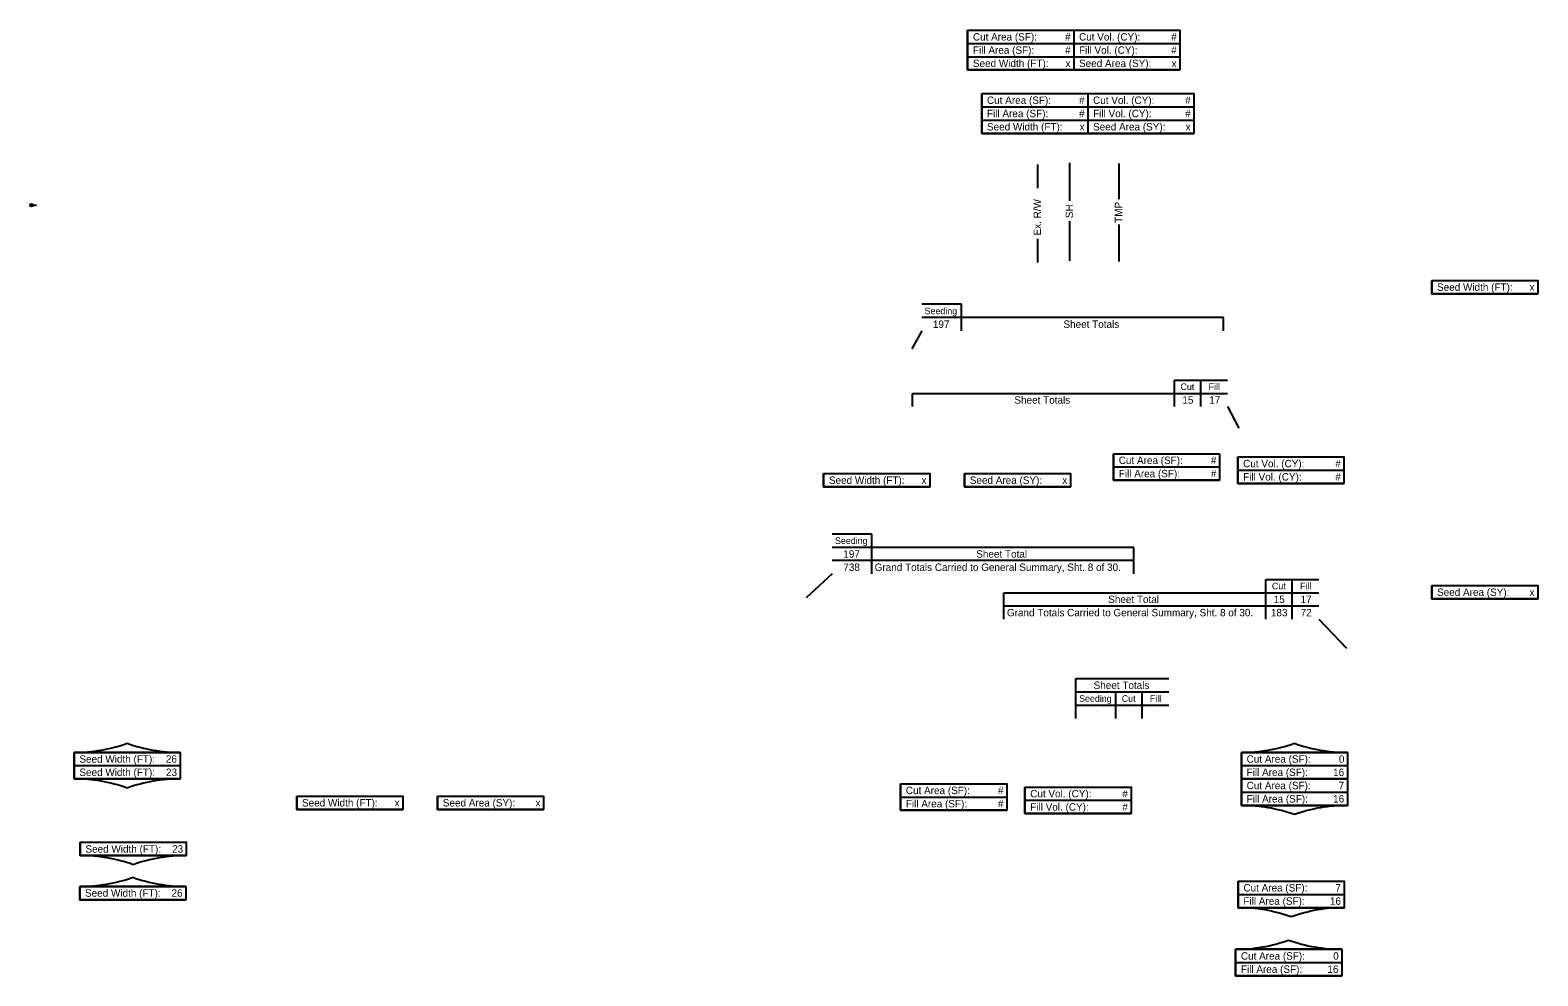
# Model space of a CAD drawing. Extents: x -475 to 76, y 0 to 417.
# Drawn here: x -32.79 to -4.37, y -0.22 to 17.6 of the extents above; entities that cross this region are included whole.
import ezdxf

# ---------------------------------------------------------------- set-up
doc = ezdxf.new("R2010")
doc.units = 0
for name, color, linetype in [('_CIVIL_CONSTRUCTION', 7, 'Continuous'), ('Default', 7, 'Continuous'), ('MT_P_Temp_Road', 7, 'Continuous'), ('RW_P_Esmt_SH', 7, 'Continuous'), ('RW_P_Esmt_TMP', 7, 'Continuous'), ('RW_X_Text', 7, 'Continuous'), ('SC_Scratch1', 7, 'Continuous'), ('SC_Scratch10', 7, 'Continuous'), ('SH_Masking', 7, 'Continuous')]:
    doc.layers.add(name, color=color, linetype=linetype)

msp = doc.modelspace()

# ---------------------------------------------------------------- linework, layer by layer
at = {"layer": '_CIVIL_CONSTRUCTION'}
for p, q in [((-32.791, 14.303), (-32.739, 14.303)), ((-32.765, 14.303), (-32.671, 14.303))]:
    msp.add_line(p, q, dxfattribs=at)
msp.add_circle((-32.765, 14.303), 0.026, dxfattribs=at)
at = {"layer": 'Default'}
for p, q in [((-15.237, 11.935), (-15.237, 12.435)), ((-10.301, 11.935), (-10.301, 12.185)), ((-11.225, 10.507), (-11.225, 11.007)), ((-10.725, 10.507), (-10.725, 11.007)), ((-16.161, 10.507), (-16.161, 10.757)), ((-16.925, 7.355), (-16.925, 8.105)), ((-11.989, 7.355), (-11.989, 7.855)), ((-17.675, 7.355), (-18.165, 6.903)), ((-9.502, 6.5), (-9.502, 7.25)), ((-9.002, 6.5), (-9.002, 7.25)), ((-14.438, 6.5), (-14.438, 7)), ((-9.502, 6.5), (-9.502, 7)), ((-8.502, 6.5), (-7.978, 5.952))]:
    msp.add_line(p, q, dxfattribs=at)
at = {"layer": 'MT_P_Temp_Road'}
for p, q in [((-15.987, 11.935), (-16.174, 11.593)), ((-10.225, 10.507), (-10.013, 10.099))]:
    msp.add_line(p, q, dxfattribs=at)
at = {"layer": 'RW_P_Esmt_SH'}
for p, q in [((-13.194, 14.388), (-13.194, 15.1)), ((-13.194, 13.254), (-13.194, 14.001))]:
    msp.add_line(p, q, dxfattribs=at)
at = {"layer": 'RW_P_Esmt_TMP'}
for p, q in [((-12.267, 14.416), (-12.267, 15.086)), ((-12.267, 13.24), (-12.267, 13.941))]:
    msp.add_line(p, q, dxfattribs=at)
at = {"layer": 'RW_X_Text'}
for p, q in [((-13.8, 14.624), (-13.8, 15.07)), ((-13.8, 13.224), (-13.8, 13.671))]:
    msp.add_line(p, q, dxfattribs=at)
at = {"layer": 'SC_Scratch1'}
for p, q in [((-15.122, 17.601), (-11.122, 17.601)), ((-15.122, 17.601), (-15.122, 16.851)), ((-15.122, 17.351), (-11.122, 17.351)), ((-13.122, 17.601), (-13.122, 16.851)), ((-11.122, 17.601), (-11.122, 16.851)), ((-15.122, 17.101), (-11.122, 17.101)), ((-15.122, 16.851), (-11.122, 16.851)), ((-14.857, 16.406), (-10.857, 16.406)), ((-14.857, 16.406), (-14.857, 15.656)), ((-12.857, 16.406), (-12.857, 15.656)), ((-10.857, 16.406), (-10.857, 15.656)), ((-14.857, 16.156), (-10.857, 16.156)), ((-14.857, 15.906), (-10.857, 15.906)), ((-14.857, 15.656), (-10.857, 15.656)), ((-6.374, 12.884), (-4.374, 12.884)), ((-6.374, 12.884), (-6.374, 12.634)), ((-4.374, 12.884), (-4.374, 12.634)), ((-6.374, 12.634), (-4.374, 12.634)), ((-15.237, 12.435), (-15.987, 12.435)), ((-10.301, 12.185), (-15.987, 12.185)), ((-11.225, 11.007), (-10.225, 11.007)), ((-16.161, 10.757), (-10.225, 10.757)), ((-12.373, 9.62), (-10.373, 9.62)), ((-12.373, 9.62), (-12.373, 9.12)), ((-10.373, 9.62), (-10.373, 9.12)), ((-10.029, 9.559), (-8.029, 9.559)), ((-10.029, 9.559), (-10.029, 9.059)), ((-8.029, 9.559), (-8.029, 9.059)), ((-17.836, 9.245), (-15.836, 9.245)), ((-17.836, 9.245), (-17.836, 8.995)), ((-15.836, 9.245), (-15.836, 8.995)), ((-15.181, 9.245), (-13.181, 9.245)), ((-15.181, 9.245), (-15.181, 8.995)), ((-13.181, 9.245), (-13.181, 8.995)), ((-12.373, 9.37), (-10.373, 9.37)), ((-12.373, 9.12), (-10.373, 9.12)), ((-10.029, 9.309), (-8.029, 9.309)), ((-17.836, 8.995), (-15.836, 8.995)), ((-15.181, 8.995), (-13.181, 8.995)), ((-10.029, 9.059), (-8.029, 9.059)), ((-16.925, 8.105), (-17.675, 8.105)), ((-11.989, 7.855), (-17.675, 7.855)), ((-11.989, 7.605), (-17.675, 7.605)), ((-9.502, 7.25), (-8.502, 7.25)), ((-6.374, 7.134), (-4.374, 7.134)), ((-6.374, 7.134), (-6.374, 6.884)), ((-4.374, 7.134), (-4.374, 6.884)), ((-14.438, 7), (-8.502, 7)), ((-6.374, 6.884), (-4.374, 6.884)), ((-14.438, 6.75), (-8.502, 6.75)), ((-13.081, 4.631), (-13.081, 5.381)), ((-13.081, 5.381), (-11.331, 5.381)), ((-13.081, 5.131), (-11.331, 5.131)), ((-12.331, 4.631), (-12.331, 5.131)), ((-11.831, 4.631), (-11.831, 5.131)), ((-13.081, 4.881), (-11.331, 4.881)), ((-12.7, 4.756), (-12.7, 4.756)), ((-12.077, 4.756), (-12.077, 4.756)), ((-11.572, 4.756), (-11.572, 4.756)), ((-31.963, 3.991), (-29.963, 3.991)), ((-31.963, 3.991), (-31.963, 3.491)), ((-29.963, 3.991), (-31.963, 3.991)), ((-29.963, 3.991), (-29.963, 3.491)), ((-9.963, 3.991), (-7.963, 3.991)), ((-9.963, 3.991), (-9.963, 3.491)), ((-7.963, 3.991), (-9.963, 3.991)), ((-7.963, 3.991), (-7.963, 3.491)), ((-31.963, 3.741), (-29.963, 3.741)), ((-9.963, 3.741), (-7.963, 3.741)), ((-31.963, 3.491), (-29.963, 3.491)), ((-29.963, 3.491), (-31.963, 3.491)), ((-9.963, 3.491), (-7.963, 3.491)), ((-9.963, 3.491), (-7.963, 3.491)), ((-9.963, 3.491), (-9.963, 2.991)), ((-7.963, 3.491), (-7.963, 2.991)), ((-27.767, 3.166), (-25.767, 3.166)), ((-27.767, 3.166), (-27.767, 2.916)), ((-25.767, 3.166), (-25.767, 2.916)), ((-25.113, 3.166), (-23.113, 3.166)), ((-25.113, 3.166), (-25.113, 2.916)), ((-23.113, 3.166), (-23.113, 2.916)), ((-16.386, 3.399), (-14.386, 3.399)), ((-16.386, 3.399), (-16.386, 2.899)), ((-16.386, 3.149), (-14.386, 3.149)), ((-14.386, 3.399), (-14.386, 2.899)), ((-14.042, 3.338), (-12.042, 3.338)), ((-14.042, 3.338), (-14.042, 2.838)), ((-12.042, 3.338), (-12.042, 2.838)), ((-9.963, 3.241), (-7.963, 3.241)), ((-27.767, 2.916), (-25.767, 2.916)), ((-25.113, 2.916), (-23.113, 2.916)), ((-16.386, 2.899), (-14.386, 2.899)), ((-14.042, 3.088), (-12.042, 3.088)), ((-9.963, 2.991), (-7.963, 2.991)), ((-7.963, 2.991), (-9.963, 2.991)), ((-14.042, 2.838), (-12.042, 2.838)), ((-31.849, 2.296), (-29.849, 2.296)), ((-31.849, 2.296), (-31.849, 2.046)), ((-29.849, 2.296), (-29.849, 2.046)), ((-29.849, 2.046), (-31.849, 2.046)), ((-31.849, 2.046), (-29.849, 2.046)), ((-29.857, 1.465), (-31.857, 1.465)), ((-31.857, 1.465), (-29.857, 1.465)), ((-31.857, 1.465), (-31.857, 1.215)), ((-29.857, 1.465), (-29.857, 1.215)), ((-10.024, 1.564), (-8.024, 1.564)), ((-10.024, 1.564), (-10.024, 1.064)), ((-8.024, 1.564), (-8.024, 1.064)), ((-31.857, 1.215), (-29.857, 1.215)), ((-10.024, 1.314), (-8.024, 1.314)), ((-10.024, 1.064), (-8.024, 1.064)), ((-8.024, 1.064), (-10.024, 1.064)), ((-10.071, 0.28), (-8.071, 0.28)), ((-10.071, 0.28), (-10.071, -0.22)), ((-8.071, 0.28), (-10.071, 0.28)), ((-10.071, 0.03), (-8.071, 0.03)), ((-8.071, 0.28), (-8.071, -0.22)), ((-10.071, -0.22), (-8.071, -0.22))]:
    msp.add_line(p, q, dxfattribs=at)
for centre, start, end in [((-31.963, 6.991), 270, 289.4712), ((-29.963, 6.991), 250.5288, 270), ((-9.963, 6.991), 270, 289.4712), ((-7.963, 6.991), 250.5288, 270), ((-31.963, 0.491), 70.5288, 90), ((-29.963, 0.491), 90, 109.4712), ((-9.963, -0.009), 70.5288, 90), ((-7.963, -0.009), 90, 109.4712), ((-31.849, -0.954), 70.5288, 90), ((-29.849, -0.954), 90, 109.4712), ((-31.857, 4.465), 270, 289.4712), ((-29.857, 4.465), 250.5288, 270), ((-10.024, -1.936), 70.5288, 90), ((-8.024, -1.936), 90, 109.4712), ((-10.071, 3.28), 270, 289.4712), ((-8.071, 3.28), 250.5288, 270)]:
    msp.add_arc(centre, 3, start, end, dxfattribs=at)
at = {"layer": 'SH_Masking'}
for points in [[(-15.122, 17.601), (-11.122, 17.601), (-11.122, 16.851), (-15.122, 16.851)], [(-14.857, 16.406), (-10.857, 16.406), (-10.857, 15.656), (-14.857, 15.656)], [(-6.374, 12.884), (-4.374, 12.884), (-4.374, 12.634), (-6.374, 12.634)], [(-12.373, 9.62), (-10.373, 9.62), (-10.373, 9.12), (-12.373, 9.12)], [(-10.029, 9.559), (-8.029, 9.559), (-8.029, 9.059), (-10.029, 9.059)], [(-17.836, 9.245), (-15.836, 9.245), (-15.836, 8.995), (-17.836, 8.995)], [(-15.181, 9.245), (-13.181, 9.245), (-13.181, 8.995), (-15.181, 8.995)], [(-6.374, 7.134), (-4.374, 7.134), (-4.374, 6.884), (-6.374, 6.884)], [(-31.963, 3.991), (-29.963, 3.991), (-29.963, 3.491), (-31.963, 3.491)], [(-9.963, 3.991), (-7.963, 3.991), (-7.963, 3.491), (-9.963, 3.491)], [(-9.963, 3.491), (-7.963, 3.491), (-7.963, 2.991), (-9.963, 2.991)], [(-27.767, 3.166), (-25.767, 3.166), (-25.767, 2.916), (-27.767, 2.916)], [(-25.113, 3.166), (-23.113, 3.166), (-23.113, 2.916), (-25.113, 2.916)], [(-16.386, 3.399), (-14.386, 3.399), (-14.386, 2.899), (-16.386, 2.899)], [(-14.042, 3.338), (-12.042, 3.338), (-12.042, 2.838), (-14.042, 2.838)], [(-31.849, 2.296), (-29.849, 2.296), (-29.849, 2.046), (-31.849, 2.046)], [(-31.857, 1.465), (-29.857, 1.465), (-29.857, 1.215), (-31.857, 1.215)], [(-10.024, 1.564), (-8.024, 1.564), (-8.024, 1.064), (-10.024, 1.064)], [(-10.071, 0.28), (-8.071, 0.28), (-8.071, -0.22), (-10.071, -0.22)]]:
    msp.add_lwpolyline(points, close=True, dxfattribs=at)

# ---------------------------------------------------------------- texts
at = {"layer": '_CIVIL_CONSTRUCTION'}
for s, p in [('855+25.00', (-32.776, 14.293)), ('1', (-32.766, 14.31)), ('CLX_RW_SR550 - 855+50.00', (-32.733, 14.31)), ('1:10', (-32.733, 14.293))]:
    msp.add_text(s, height=0.00328, dxfattribs=at).set_placement(p)
at = {"layer": 'Default'}
for s, height, p in [('Seeding', 0.125, (-15.933, 12.247)), ('197', 0.14, (-15.777, 11.99)), ('Sheet Totals', 0.14, (-13.316, 11.99)), ('Cut', 0.125, (-11.11, 10.819)), ('Fill', 0.125, (-10.58, 10.819)), ('Sheet Totals', 0.14, (-14.24, 10.562)), ('15', 0.14, (-11.075, 10.562)), ('17', 0.14, (-10.569, 10.562)), ('Seeding', 0.125, (-17.621, 7.918)), ('197', 0.14, (-17.465, 7.66)), ('Sheet Total', 0.14, (-14.959, 7.66)), ('738', 0.14, (-17.465, 7.41)), ('Grand Totals Carried to General Summary, Sht. 8 of 30.', 0.14, (-16.874, 7.41)), ('Cut', 0.125, (-9.387, 7.063)), ('Fill', 0.125, (-8.857, 7.063)), ('Sheet Total', 0.14, (-12.472, 6.805)), ('15', 0.14, (-9.352, 6.805)), ('17', 0.14, (-8.846, 6.805)), ('Grand Totals Carried to General Summary, Sht. 8 of 30.', 0.14, (-14.381, 6.555)), ('183', 0.14, (-9.406, 6.555)), ('72', 0.14, (-8.845, 6.555))]:
    msp.add_text(s, height=height, dxfattribs=at).set_placement(p)
at = {"layer": 'RW_P_Esmt_SH'}
msp.add_text('SH', height=0.14, rotation=90, dxfattribs=at).set_placement((-13.135, 14.058))
at = {"layer": 'RW_P_Esmt_TMP'}
msp.add_text('TMP', height=0.14, rotation=90, dxfattribs=at).set_placement((-12.208, 13.97))
at = {"layer": 'RW_X_Text'}
msp.add_text('Ex. R/W', height=0.14, rotation=90, dxfattribs=at).set_placement((-13.74, 13.731))
at = {"layer": 'SC_Scratch1'}
for s, height, p in [('Sheet Totals', 0.14, (-12.747, 5.186)), ('Seeding', 0.125, (-13.021, 4.943)), ('Cut', 0.125, (-12.217, 4.943)), ('Fill', 0.125, (-11.687, 4.943))]:
    msp.add_text(s, height=height, dxfattribs=at).set_placement(p)
at = {"layer": 'SC_Scratch10'}
for s, p in [('Cut Area (SF):', (-15.022, 17.406)), ('#', (-13.285, 17.406)), ('Cut Vol. (CY):', (-13.022, 17.406)), ('#', (-11.285, 17.406)), ('Seed Width (FT):', (-15.022, 16.906)), ('Fill Area (SF):', (-15.022, 17.156)), ('#', (-13.285, 17.156)), ('Seed Area (SY):', (-13.022, 16.906)), ('Fill Vol. (CY):', (-13.022, 17.156)), ('#', (-11.285, 17.156)), ('x', (-13.277, 16.906)), ('x', (-11.277, 16.906)), ('Cut Area (SF):', (-14.757, 16.211)), ('#', (-13.021, 16.211)), ('Cut Vol. (CY):', (-12.757, 16.211)), ('#', (-11.021, 16.211)), ('Fill Area (SF):', (-14.757, 15.961)), ('#', (-13.021, 15.961)), ('Fill Vol. (CY):', (-12.757, 15.961)), ('#', (-11.021, 15.961)), ('Seed Width (FT):', (-14.757, 15.711)), ('x', (-13.012, 15.711)), ('Seed Area (SY):', (-12.757, 15.711)), ('x', (-11.012, 15.711)), ('Seed Width (FT):', (-6.274, 12.689)), ('x', (-4.53, 12.689)), ('Cut Area (SF):', (-12.273, 9.425)), ('#', (-10.537, 9.425)), ('Cut Vol. (CY):', (-9.929, 9.364)), ('#', (-8.193, 9.364)), ('Seed Width (FT):', (-17.736, 9.05)), ('x', (-15.991, 9.05)), ('Seed Area (SY):', (-15.081, 9.05)), ('x', (-13.337, 9.05)), ('Fill Area (SF):', (-12.273, 9.175)), ('#', (-10.537, 9.175)), ('Fill Vol. (CY):', (-9.929, 9.114)), ('#', (-8.193, 9.114)), ('Seed Area (SY):', (-6.274, 6.939)), ('x', (-4.53, 6.939)), ('Seed Width (FT):', (-31.863, 3.796)), ('26', (-30.233, 3.796)), ('Cut Area (SF):', (-9.863, 3.796)), ('0', (-8.124, 3.796)), ('Seed Width (FT):', (-31.863, 3.546)), ('23', (-30.231, 3.546)), ('Cut Area (SF):', (-9.863, 3.296)), ('Fill Area (SF):', (-9.863, 3.546)), ('16', (-8.233, 3.546)), ('7', (-8.13, 3.296)), ('Cut Area (SF):', (-16.286, 3.204)), ('#', (-14.55, 3.204)), ('Cut Vol. (CY):', (-13.942, 3.143)), ('#', (-12.206, 3.143)), ('Fill Area (SF):', (-9.863, 3.046)), ('16', (-8.233, 3.046)), ('Seed Width (FT):', (-27.667, 2.971)), ('x', (-25.923, 2.971)), ('Seed Area (SY):', (-25.013, 2.971)), ('x', (-23.268, 2.971)), ('Fill Area (SF):', (-16.286, 2.954)), ('#', (-14.55, 2.954)), ('Fill Vol. (CY):', (-13.942, 2.893)), ('#', (-12.206, 2.893)), ('Seed Width (FT):', (-31.749, 2.101)), ('23', (-30.116, 2.101)), ('Cut Area (SF):', (-9.924, 1.369)), ('7', (-8.191, 1.369)), ('Seed Width (FT):', (-31.757, 1.27)), ('26', (-30.127, 1.27)), ('Fill Area (SF):', (-9.924, 1.119)), ('16', (-8.294, 1.119)), ('Cut Area (SF):', (-9.971, 0.085)), ('0', (-8.232, 0.085)), ('Fill Area (SF):', (-9.971, -0.165)), ('16', (-8.341, -0.165))]:
    msp.add_text(s, height=0.14, dxfattribs=at).set_placement(p)

doc.saveas('drawing.dxf')
